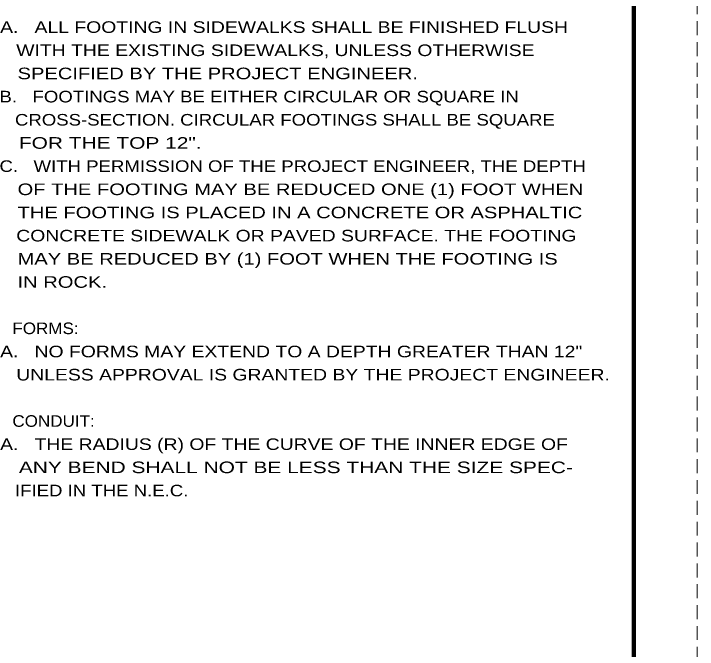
# Model space of a CAD drawing. Extents: x -560 to 120, y 26 to 466.
# Drawn here: x 2.1 to 120.2, y 245.8 to 355.5 of the extents above; entities that cross this region are included whole.
import ezdxf

# ---------------------------------------------------------------- set-up
doc = ezdxf.new("R2010")
doc.units = 0
doc.header["$LTSCALE"] = 0.8
doc.linetypes.add('MEDIUM_DASHED', pattern=[4.5, 3, -1.5])
doc.layers.add('1', color=7, linetype='Continuous', lineweight=53)
doc.layers.add('61', color=7, linetype='Continuous', lineweight=35)

msp = doc.modelspace()

# ---------------------------------------------------------------- linework, layer by layer
at = {"layer": '1', "linetype": 'MEDIUM_DASHED', "lineweight": 13}
msp.add_line((120.2391, 465.8427), (120.2191, 25.8227), dxfattribs=at)
at = {"layer": '61', "lineweight": 158}
msp.add_line((109.2591, 455.8427), (109.2791, 35.8027), dxfattribs=at)

# ---------------------------------------------------------------- texts
at = {"layer": '1'}
for s, width, p in [('   A.   ALL FOOTING IN SIDEWALKS SHALL BE FINISHED FLUSH', 1.25, (-2.9781, 352.233)), ('      WITH THE EXISTING SIDEWALKS, UNLESS OTHERWISE', 1.25, (-2.9781, 348.233)), ('      SPECIFIED BY THE PROJECT ENGINEER.', 1.3, (-2.9781, 344.233)), ('   B.   FOOTINGS MAY BE EITHER CIRCULAR OR SQUARE IN', 1.2, (-2.9781, 340.233)), ('      CROSS-SECTION. CIRCULAR FOOTINGS SHALL BE SQUARE', 1.2, (-2.9781, 336.233)), ('      FOR THE TOP 12".', 1.35, (-2.9781, 332.233)), ('   C.   WITH PERMISSION OF THE PROJECT ENGINEER, THE DEPTH', 1.2, (-2.9781, 328.233)), ('      OF THE FOOTING MAY BE REDUCED ONE (1) FOOT WHEN', 1.3, (-2.9781, 324.233)), ('      THE FOOTING IS PLACED IN A CONCRETE OR ASPHALTIC', 1.3, (-2.9781, 320.233)), ('      CONCRETE SIDEWALK OR PAVED SURFACE. THE FOOTING', 1.25, (-2.9781, 316.233)), ('      MAY BE REDUCED BY (1) FOOT WHEN THE FOOTING IS', 1.3, (-2.9781, 312.233)), ('      IN ROCK.', 1.3, (-2.9781, 308.233)), ('4.   FORMS:', 1.1, (-2.9781, 300.233)), ('   A.   NO FORMS MAY EXTEND TO A DEPTH GREATER THAN 12"', 1.25, (-2.9781, 296.233)), ('      UNLESS APPROVAL IS GRANTED BY THE PROJECT ENGINEER.', 1.25, (-2.9781, 292.233)), ('5.   CONDUIT:', 1.1, (-2.9781, 284.233)), ('   A.   THE RADIUS (R) OF THE CURVE OF THE INNER EDGE OF', 1.25, (-2.9781, 280.233)), ('      ANY BEND SHALL NOT BE LESS THAN THE SIZE SPEC-', 1.35, (-2.9781, 276.233)), ('      IFIED IN THE N.E.C.   ', 1.2, (-2.9781, 272.233))]:
    msp.add_text(s, height=2, dxfattribs=dict(at, width=width)).set_placement(p)

doc.saveas('drawing.dxf')
